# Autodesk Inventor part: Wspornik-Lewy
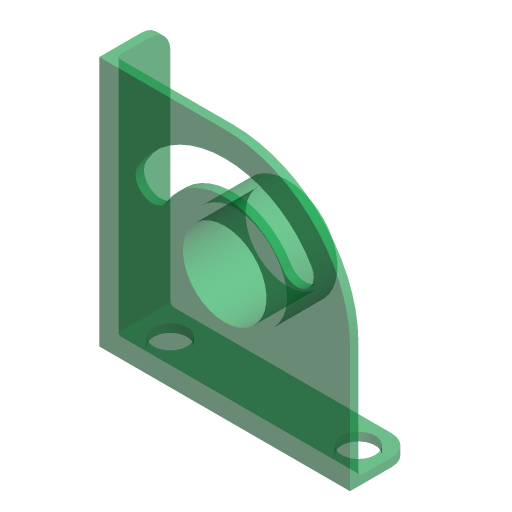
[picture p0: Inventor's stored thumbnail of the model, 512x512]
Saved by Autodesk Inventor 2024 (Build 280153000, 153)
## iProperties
Company: ATC
Shininess: 0.0
Length Units: 11269
Angle Units: 11279
Time Units: 11290
Mass Units: 11283
Length Display Precision: 3
Angle Display Precision: 2
Compacted: True
Created: 2023-03
Part Number: Wspornik-Lewy
Document SubType Name: Modeling
Designer: Andrzej Jaskulski
Density: 1 g/cm^3
Material: Ogólny
Appearance: Green(Clear)
Checked By: A.J.
Engr Approved By: Andrzej Jaskulski
Mfg Approved By: Andrzej Jaskulski
Authority: A.J.
Density: 0.0
Volumn: 0.0
Area: 0.0
PropertySet Name: Model Information
Control State: 0
Master: False
Checked Out: False
Title: A.J.: Kurs R2024-MEP
Author: Andrzej Jaskulski
Revision Number: 1/24
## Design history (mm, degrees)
node "Extrusion1" dims "d0" = 0, "d1" = 15
node "Hole1" dims "d5" = 118 deg, "d6" = 60 deg, "d7" = 2, "d8" = 4, "d9" = 8, "d10" = 20
node "Fillet1" dims "d11" = 5
node "Fillet2" dims "d12" = 30
node "Shell1" dims "d13" = 2
node "Extrusion2" dims "d18" = 10, "d19" = 0
node "Hole2" dims "d24" = 8, "d25" = 4, "d26" = 2, "d27" = 60 deg, "d28" = 8, "d29" = 118 deg
node "Chamfer1" dims "d30" = 1, "d31" = 1, "d33" = 45 deg
node "Fillet3" dims "d32" = 1
node "Bryła1"
node "Korpusy bryłowe"
node "Korpusy powierzchniowe"
sketch "Sketch2"
  geometry: L1 (0, 0)-(60, 0); L2 (60, 0)-(60, 60); L3 (60, 60)-(0, 60); L4 (0, 60)-(0, 0)
  constraints: 8 end point, 2 parallel, 2 perpendicular, 1 horizontal, 1 other
  dimensions: "d2" = 60 distance of L1.start L1.end
sketch "Sketch3"
  geometry: L1 (0, 0)-(60, 0) reference; L2 (0, 60)-(0, 0) reference; 1 further point
  dimensions: "d4" = 30 distance from line of L1 point (30, 30); "d3" = 30 distance from line of L2 point (30, 30)
sketch "Sketch4"
  geometry: L1 (60, 30)-(60, 0) reference; L2 (30, 30)-(30, 63.901); L3 (30, 30)-(61.068, 47.937); L4 (30, 30)-(-2.571, 48.805); C1 r 10 at (30, 30) reference; A1 r 16 centre (30, 30) between (43.856, 38) and (16.144, 38); A2 r 24 centre (30, 30) between (50.785, 42) and (9.215, 42); A3 r 4 centre (12.679, 40) between (9.215, 42) and (16.144, 38); A4 r 4 centre (47.321, 40) between (43.856, 38) and (50.785, 42)
  constraints: 8 point on circle, 6 end point, 4 centre point, 4 point on line, 2 coincident, 2 tangent, 1 parallel
  dimensions: "d14" = 60 deg angle of L2 L3; "d15" = 60 deg angle of L4 L2 (= d14); "d16" = 16 radius of A1; "d17" = 24 radius of A2
sketch "Sketch5"
  geometry: L1 (0, 13)-(53, 13) reference; L2 (0, 13)-(0, 0) reference; L3 (6.5, 6.5)-(51.5, 6.5)
  constraints: 2 end point, 1 parallel
  dimensions: "d21" = 6.5 distance between parallel lines of L1 L3; "d22" = 6.5 distance from line of L2 L3.start; "d23" = 45 distance of L3.start L3.end
